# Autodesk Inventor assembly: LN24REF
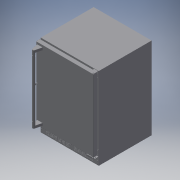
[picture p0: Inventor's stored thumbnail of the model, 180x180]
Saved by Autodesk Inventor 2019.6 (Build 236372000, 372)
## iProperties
Company: none
Created: 2025-04
Part Number: LN24REF
Description: CATIA V5 STEP
Document SubType Name: Assembly
Designer: MMAK
Authority: none
Title: C:\Users\MMAK\Documents\SmarTeam\WEBSITE CAD\Lynx STP\LN24REF.stp
Author: none
Sending System: CATIA V5 STEP AP203 v2
Preprocessor: CATIA Unofficial Packaging Version SP2
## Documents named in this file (4)
- C:\Users\MMAK\Documents\SmarTeam\WEBSITE CAD\Lynx STP\LN24REF.iam
- C:\Users\MMAK\Documents\SmarTeam\WEBSITE CAD\Lynx STP\VORE224-SS41A.iam
- C:\Users\MMAK\Documents\SmarTeam\WEBSITE CAD\Lynx STP\OC UC 24.ipt
- C:\Users\MMAK\Documents\SmarTeam\WEBSITE CAD\Lynx STP\Product90.iam
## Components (3 placed, 3 different names)
1. VORE224-SS41A.1 [sub-assembly]
2. OC UC 24.1
3. Product90.2 [sub-assembly]
